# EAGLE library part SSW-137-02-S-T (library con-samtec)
THROUGH-HOLE .025" SQ POST SOCKET Source: Samtec SSW.pdf
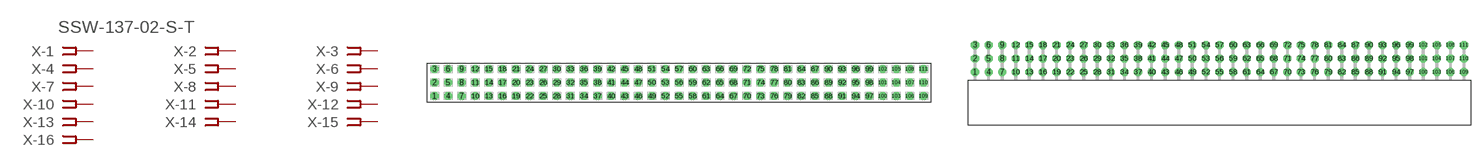
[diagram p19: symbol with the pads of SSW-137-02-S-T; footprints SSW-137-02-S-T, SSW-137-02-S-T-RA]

Designator prefix X; gates -1=FPINV -2=FPIN -3=FPIN -4=FPIN -5=FPIN -6=FPIN -7=FPIN -8=FPIN -9=FPIN -10=FPIN -11=FPIN -12=FPIN -13=FPIN -14=FPIN -15=FPIN -16=FPIN -17=FPIN -18=FPIN -19=FPIN -20=FPIN -21=FPIN -22=FPIN -23=FPIN -24=FPIN -25=FPIN -26=FPIN -27=FPIN -28=FPIN -29=FPIN -30=FPIN -31=FPIN -32=FPIN -33=FPIN -34=FPIN -35=FPIN -36=FPIN -37=FPIN -38=FPIN -39=FPIN -40=FPIN -41=FPIN -42=FPIN -43=FPIN -44=FPIN -45=FPIN -46=FPIN -47=FPIN -48=FPIN -49=FPIN -50=FPIN -51=FPIN -52=FPIN -53=FPIN -54=FPIN -55=FPIN -56=FPIN -57=FPIN -58=FPIN -59=FPIN -60=FPIN -61=FPIN -62=FPIN -63=FPIN -64=FPIN -65=FPIN -66=FPIN -67=FPIN -68=FPIN -69=FPIN -70=FPIN -71=FPIN -72=FPIN -73=FPIN -74=FPIN -75=FPIN -76=FPIN -77=FPIN -78=FPIN -79=FPIN -80=FPIN -81=FPIN -82=FPIN -83=FPIN -84=FPIN -85=FPIN -86=FPIN -87=FPIN -88=FPIN -89=FPIN -90=FPIN -91=FPIN -92=FPIN -93=FPIN -94=FPIN -95=FPIN -96=FPIN -97=FPIN -98=FPIN -99=FPIN -100=FPIN -101=FPIN -102=FPIN -103=FPIN -104=FPIN -105=FPIN -106=FPIN -107=FPIN -108=FPIN -109=FPIN -110=FPIN -111=FPIN

## SSW-137-02-S-T (OC_FARNELL: unknown; OC_NEWARK: unknown)  [SSW-137-02-S-T]
1  -1:1  pas
2  -2:1  pas
3  -3:1  pas
4  -4:1  pas
5  -5:1  pas
6  -6:1  pas
7  -7:1  pas
8  -8:1  pas
9  -9:1  pas
10  -10:1  pas
11  -11:1  pas
12  -12:1  pas
13  -13:1  pas
14  -14:1  pas
15  -15:1  pas
16  -16:1  pas
17  -17:1  pas
18  -18:1  pas
19  -19:1  pas
20  -20:1  pas
21  -21:1  pas
22  -22:1  pas
23  -23:1  pas
24  -24:1  pas
25  -25:1  pas
26  -26:1  pas
27  -27:1  pas
28  -28:1  pas
29  -29:1  pas
30  -30:1  pas
31  -31:1  pas
32  -32:1  pas
33  -33:1  pas
34  -34:1  pas
35  -35:1  pas
36  -36:1  pas
37  -37:1  pas
38  -38:1  pas
39  -39:1  pas
40  -40:1  pas
41  -41:1  pas
42  -42:1  pas
43  -43:1  pas
44  -44:1  pas
45  -45:1  pas
46  -46:1  pas
47  -47:1  pas
48  -48:1  pas
49  -49:1  pas
50  -50:1  pas
51  -51:1  pas
52  -52:1  pas
53  -53:1  pas
54  -54:1  pas
55  -55:1  pas
56  -56:1  pas
57  -57:1  pas
58  -58:1  pas
59  -59:1  pas
60  -60:1  pas
61  -61:1  pas
62  -62:1  pas
63  -63:1  pas
64  -64:1  pas
65  -65:1  pas
66  -66:1  pas
67  -67:1  pas
68  -68:1  pas
69  -69:1  pas
70  -70:1  pas
71  -71:1  pas
72  -72:1  pas
73  -73:1  pas
74  -74:1  pas
75  -75:1  pas
76  -76:1  pas
77  -77:1  pas
78  -78:1  pas
79  -79:1  pas
80  -80:1  pas
81  -81:1  pas
82  -82:1  pas
83  -83:1  pas
84  -84:1  pas
85  -85:1  pas
86  -86:1  pas
87  -87:1  pas
88  -88:1  pas
89  -89:1  pas
90  -90:1  pas
91  -91:1  pas
92  -92:1  pas
93  -93:1  pas
94  -94:1  pas
95  -95:1  pas
96  -96:1  pas
97  -97:1  pas
98  -98:1  pas
99  -99:1  pas
100  -100:1  pas
101  -101:1  pas
102  -102:1  pas
103  -103:1  pas
104  -104:1  pas
105  -105:1  pas
106  -106:1  pas
107  -107:1  pas
108  -108:1  pas
109  -109:1  pas
110  -110:1  pas
111  -111:1  pas

## SSW-137-02-S-TRA (OC_FARNELL: unknown; OC_NEWARK: unknown)  [SSW-137-02-S-T-RA]
Pads as for SSW-137-02-S-T

## Footprint SSW-137-02-S-T (pad centres in mm)
THROUGH-HOLE .025" SQ POST SOCKET Source: Samtec SSW.pdf
drill 1 pad 1.5 octagon: 1 -45.72,-2.54; 2 -45.72,0; 3 -45.72,2.54; 4 -43.18,-2.54; 5 -43.18,0; 6 -43.18,2.54; 7 -40.64,-2.54; 8 -40.64,0; 9 -40.64,2.54; 10 -38.1,-2.54; 11 -38.1,0; 12 -38.1,2.54; 13 -35.56,-2.54; 14 -35.56,0; 15 -35.56,2.54; 16 -33.02,-2.54; 17 -33.02,0; 18 -33.02,2.54; 19 -30.48,-2.54; 20 -30.48,0; 21 -30.48,2.54; 22 -27.94,-2.54; 23 -27.94,0; 24 -27.94,2.54; 25 -25.4,-2.54; 26 -25.4,0; 27 -25.4,2.54; 28 -22.86,-2.54; 29 -22.86,0; 30 -22.86,2.54; 31 -20.32,-2.54; 32 -20.32,0; 33 -20.32,2.54; 34 -17.78,-2.54; 35 -17.78,0; 36 -17.78,2.54; 37 -15.24,-2.54; 38 -15.24,0; 39 -15.24,2.54; 40 -12.7,-2.54; 41 -12.7,0; 42 -12.7,2.54; 43 -10.16,-2.54; 44 -10.16,0; 45 -10.16,2.54; 46 -7.62,-2.54; 47 -7.62,0; 48 -7.62,2.54; 49 -5.08,-2.54; 50 -5.08,0; 51 -5.08,2.54; 52 -2.54,-2.54; 53 -2.54,0; 54 -2.54,2.54; 55 0,-2.54; 56 0,0; 57 0,2.54; 58 2.54,-2.54; 59 2.54,0; 60 2.54,2.54; 61 5.08,-2.54; 62 5.08,0; 63 5.08,2.54; 64 7.62,-2.54; 65 7.62,0; 66 7.62,2.54; 67 10.16,-2.54; 68 10.16,0; 69 10.16,2.54; 70 12.7,-2.54; 71 12.7,0; 72 12.7,2.54; 73 15.24,-2.54; 74 15.24,0; 75 15.24,2.54; 76 17.78,-2.54; 77 17.78,0; 78 17.78,2.54; 79 20.32,-2.54; 80 20.32,0; 81 20.32,2.54; 82 22.86,-2.54; 83 22.86,0; 84 22.86,2.54; 85 25.4,-2.54; 86 25.4,0; 87 25.4,2.54; 88 27.94,-2.54; 89 27.94,0; 90 27.94,2.54; 91 30.48,-2.54; 92 30.48,0; 93 30.48,2.54; 94 33.02,-2.54; 95 33.02,0; 96 33.02,2.54; 97 35.56,-2.54; 98 35.56,0; 99 35.56,2.54; 100 38.1,-2.54; 101 38.1,0; 102 38.1,2.54; 103 40.64,-2.54; 104 40.64,0; 105 40.64,2.54; 106 43.18,-2.54; 107 43.18,0; 108 43.18,2.54; 109 45.72,-2.54; 110 45.72,0; 111 45.72,2.54

## Footprint SSW-137-02-S-T-RA (pad centres in mm)
THROUGH-HOLE .025" SQ POST SOCKET Source: Samtec SSW.pdf
drill 1 pad 1.5 octagon: 1 -45.72,1.524; 2 -45.72,4.064; 3 -45.72,6.604; 4 -43.18,1.524; 5 -43.18,4.064; 6 -43.18,6.604; 7 -40.64,1.524; 8 -40.64,4.064; 9 -40.64,6.604; 10 -38.1,1.524; 11 -38.1,4.064; 12 -38.1,6.604; 13 -35.56,1.524; 14 -35.56,4.064; 15 -35.56,6.604; 16 -33.02,1.524; 17 -33.02,4.064; 18 -33.02,6.604; 19 -30.48,1.524; 20 -30.48,4.064; 21 -30.48,6.604; 22 -27.94,1.524; 23 -27.94,4.064; 24 -27.94,6.604; 25 -25.4,1.524; 26 -25.4,4.064; 27 -25.4,6.604; 28 -22.86,1.524; 29 -22.86,4.064; 30 -22.86,6.604; 31 -20.32,1.524; 32 -20.32,4.064; 33 -20.32,6.604; 34 -17.78,1.524; 35 -17.78,4.064; 36 -17.78,6.604; 37 -15.24,1.524; 38 -15.24,4.064; 39 -15.24,6.604; 40 -12.7,1.524; 41 -12.7,4.064; 42 -12.7,6.604; 43 -10.16,1.524; 44 -10.16,4.064; 45 -10.16,6.604; 46 -7.62,1.524; 47 -7.62,4.064; 48 -7.62,6.604; 49 -5.08,1.524; 50 -5.08,4.064; 51 -5.08,6.604; 52 -2.54,1.524; 53 -2.54,4.064; 54 -2.54,6.604; 55 0,1.524; 56 0,4.064; 57 0,6.604; 58 2.54,1.524; 59 2.54,4.064; 60 2.54,6.604; 61 5.08,1.524; 62 5.08,4.064; 63 5.08,6.604; 64 7.62,1.524; 65 7.62,4.064; 66 7.62,6.604; 67 10.16,1.524; 68 10.16,4.064; 69 10.16,6.604; 70 12.7,1.524; 71 12.7,4.064; 72 12.7,6.604; 73 15.24,1.524; 74 15.24,4.064; 75 15.24,6.604; 76 17.78,1.524; 77 17.78,4.064; 78 17.78,6.604; 79 20.32,1.524; 80 20.32,4.064; 81 20.32,6.604; 82 22.86,1.524; 83 22.86,4.064; 84 22.86,6.604; 85 25.4,1.524; 86 25.4,4.064; 87 25.4,6.604; 88 27.94,1.524; 89 27.94,4.064; 90 27.94,6.604; 91 30.48,1.524; 92 30.48,4.064; 93 30.48,6.604; 94 33.02,1.524; 95 33.02,4.064; 96 33.02,6.604; 97 35.56,1.524; 98 35.56,4.064; 99 35.56,6.604; 100 38.1,1.524; 101 38.1,4.064; 102 38.1,6.604; 103 40.64,1.524; 104 40.64,4.064; 105 40.64,6.604; 106 43.18,1.524; 107 43.18,4.064; 108 43.18,6.604; 109 45.72,1.524; 110 45.72,4.064; 111 45.72,6.604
